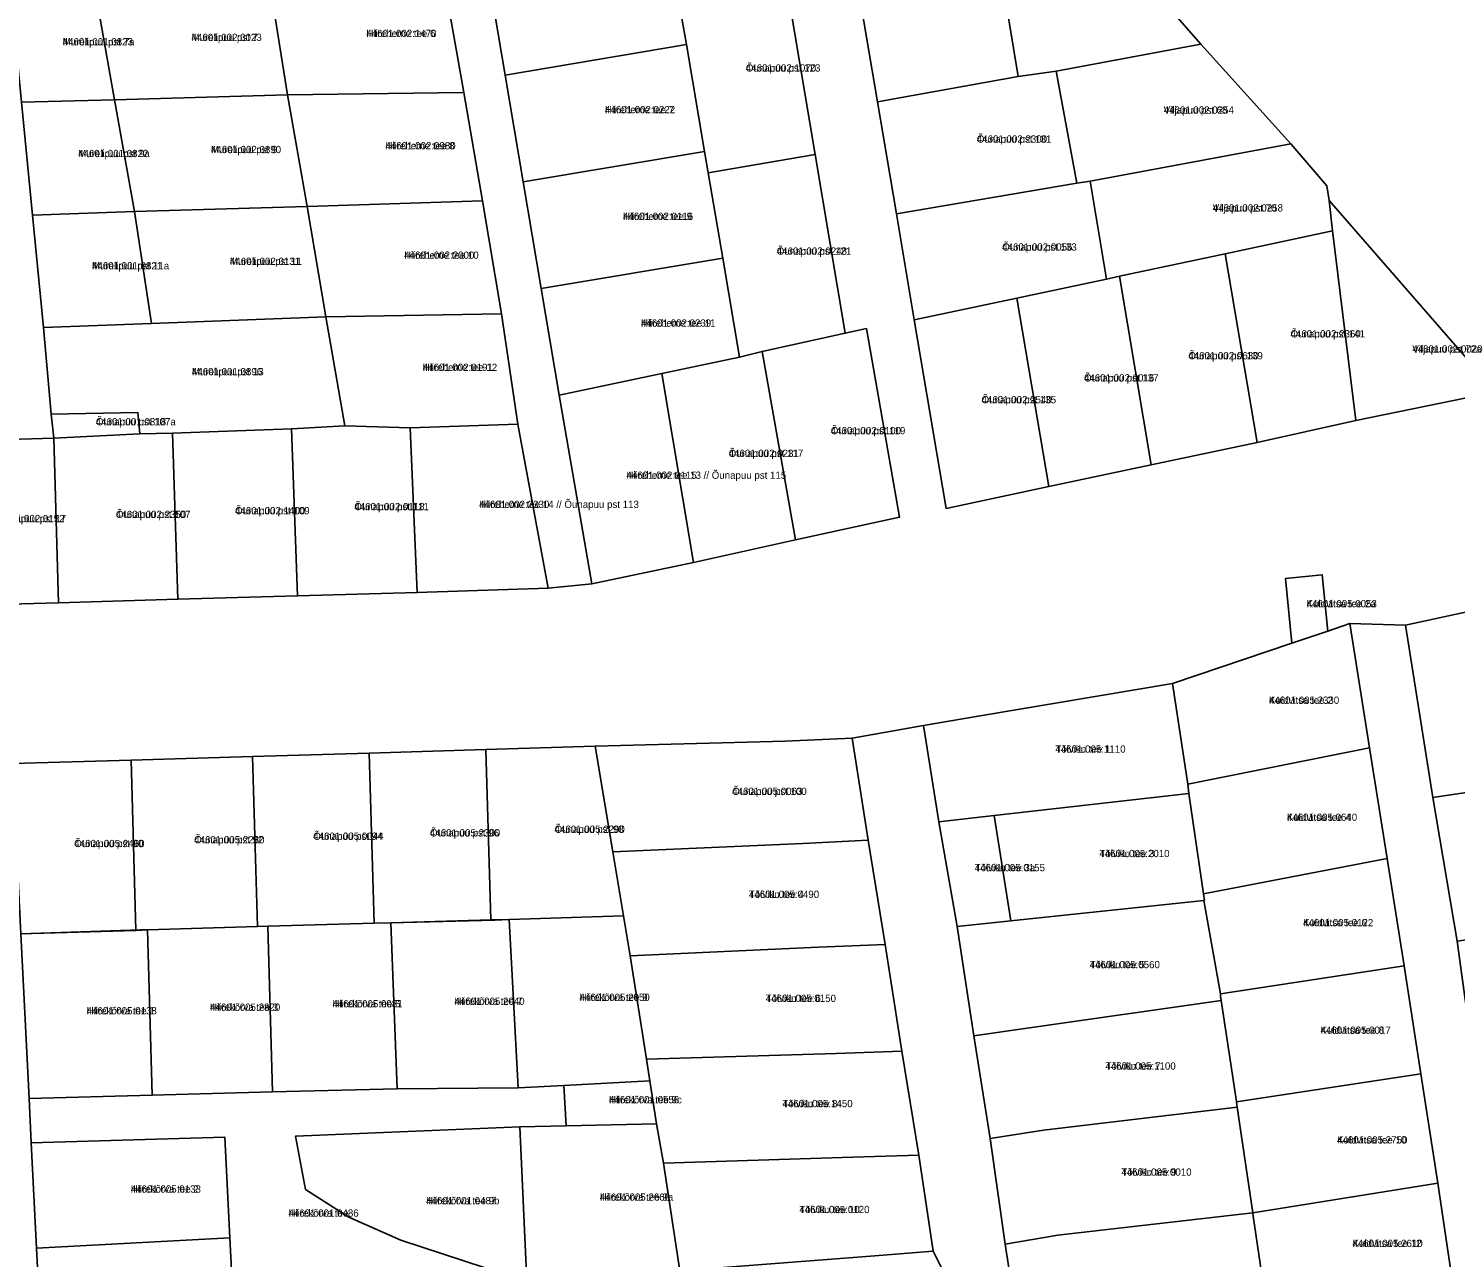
# Model space of a CAD drawing. Extents: x 551843 to 558501, y 6589003 to 6595718.
# Drawn here: x 553189.3 to 553484, y 6593051.3 to 6593305.2 of the extents above; entities that cross this region are included whole.
import ezdxf

# ---------------------------------------------------------------- set-up
doc = ezdxf.new("R2010")
doc.units = 0
for name, color, linetype in [('L_AADRESS', 7, 'Continuous'), ('PIIR', 7, 'Continuous'), ('TUNNUS', 7, 'Continuous')]:
    doc.layers.add(name, color=color, linetype=linetype)

msp = doc.modelspace()

# ---------------------------------------------------------------- linework, layer by layer
at = {"layer": 'PIIR'}
for points in [[(553431.44, 6593301.98), (553401.54, 6593296.36), (553393.68, 6593295.28), (553388.85, 6593324.58), (553408.59, 6593328.1)], [(553321.43, 6593323.96), (553323.14, 6593313.55), (553325.22, 6593301.86), (553287.76, 6593295.55), (553284.04, 6593317.59)], [(553372.85, 6593321.87), (553388.85, 6593324.58), (553393.68, 6593295.28), (553364.64, 6593290.06), (553359.64, 6593319.64)], [(553345.35, 6593317.22), (553351.79, 6593279.16), (553329.7, 6593275.35), (553328.94, 6593279.82), (553325.22, 6593301.86), (553323.14, 6593313.55)], [(553187.87, 6593289.99), (553185.68, 6593312.77), (553202.98, 6593313.47), (553207.03, 6593290.47)], [(553202.98, 6593313.47), (553239.02, 6593314.75), (553239.24, 6593314.02), (553242.8, 6593291.47), (553207.03, 6593290.47)], [(553242.8, 6593291.47), (553239.24, 6593314.02), (553275.11, 6593315.4), (553279.23, 6593292.01)], [(553287.76, 6593295.55), (553325.22, 6593301.86), (553328.94, 6593279.82), (553291.46, 6593273.51)], [(553401.54, 6593296.36), (553431.44, 6593301.98), (553449.98, 6593281.34), (553408.55, 6593273.65), (553405.8, 6593273.23)], [(553393.68, 6593295.28), (553401.54, 6593296.36), (553405.8, 6593273.23), (553368.56, 6593266.89), (553364.64, 6593290.06)], [(553190.11, 6593266.63), (553187.87, 6593289.99), (553207.03, 6593290.47), (553211.2, 6593267.42)], [(553246.86, 6593268.44), (553211.2, 6593267.42), (553207.03, 6593290.47), (553242.8, 6593291.47)], [(553246.86, 6593268.44), (553242.8, 6593291.47), (553279.23, 6593292.01), (553283.03, 6593269.62)], [(553408.55, 6593273.65), (553449.98, 6593281.34), (553457.44, 6593272.71), (553457.9, 6593269.64), (553458.6, 6593263.38), (553436.48, 6593258.67), (553414.6, 6593254.02), (553411.95, 6593253.44)], [(553328.94, 6593279.82), (553329.7, 6593275.35), (553332.67, 6593257.78), (553295.2, 6593251.47), (553291.46, 6593273.51)], [(553329.7, 6593275.35), (553351.79, 6593279.16), (553357.97, 6593242.25), (553340.79, 6593238.48), (553336.12, 6593237.33), (553332.67, 6593257.78)], [(553405.8, 6593273.23), (553408.55, 6593273.65), (553411.95, 6593253.44), (553393.42, 6593249.5), (553372.24, 6593245), (553368.56, 6593266.89)], [(553250.72, 6593245.64), (553246.86, 6593268.44), (553283.03, 6593269.62), (553286.99, 6593246.23)], [(553492.32, 6593230.16), (553463.41, 6593224.22), (553458.6, 6593263.38), (553457.9, 6593269.64)], [(553192.39, 6593243.41), (553190.11, 6593266.63), (553211.2, 6593267.42), (553214.71, 6593244.27)], [(553246.86, 6593268.44), (553250.72, 6593245.64), (553214.71, 6593244.27), (553211.2, 6593267.42)], [(553436.48, 6593258.67), (553458.6, 6593263.38), (553463.41, 6593224.22), (553443.08, 6593219.69)], [(553295.2, 6593251.47), (553332.67, 6593257.78), (553336.12, 6593237.33), (553320.1, 6593233.93), (553298.93, 6593229.44)], [(553436.48, 6593258.67), (553443.08, 6593219.69), (553421.19, 6593215.04), (553414.6, 6593254.02)], [(553400.02, 6593210.56), (553393.42, 6593249.5), (553411.95, 6593253.44), (553414.6, 6593254.02), (553421.19, 6593215.04)], [(553393.42, 6593249.5), (553400.02, 6593210.56), (553378.84, 6593206.06), (553372.24, 6593245)], [(553194.01, 6593225.56), (553192.39, 6593243.41), (553214.71, 6593244.27), (553250.72, 6593245.64), (553254.64, 6593223.14), (553243.59, 6593222.5), (553219.07, 6593221.61), (553212.31, 6593221.49), (553211.91, 6593225.86)], [(553250.72, 6593245.64), (553286.99, 6593246.23), (553290.38, 6593223.46), (553268.1, 6593222.69), (553254.64, 6593223.14)], [(553362.34, 6593243.2), (553369.22, 6593204.23), (553347.73, 6593199.6), (553340.79, 6593238.48), (553357.97, 6593242.25)], [(553320.1, 6593233.93), (553336.12, 6593237.33), (553340.79, 6593238.48), (553347.73, 6593199.6), (553326.66, 6593194.9)], [(553320.1, 6593233.93), (553326.66, 6593194.9), (553305.62, 6593190.48), (553298.93, 6593229.44)], [(553194.01, 6593225.56), (553211.91, 6593225.86), (553212.31, 6593221.49), (553194.54, 6593220.58)], [(553212.31, 6593221.49), (553219.07, 6593221.61), (553220.17, 6593187.29), (553195.51, 6593186.59), (553194.54, 6593220.58)], [(553219.07, 6593221.61), (553243.59, 6593222.5), (553244.84, 6593187.99), (553220.17, 6593187.29)], [(553243.59, 6593222.5), (553254.64, 6593223.14), (553268.1, 6593222.69), (553269.6, 6593188.68), (553244.84, 6593187.99)], [(553290.38, 6593223.46), (553296.62, 6593189.61), (553269.6, 6593188.68), (553268.1, 6593222.69)], [(553168.98, 6593219.85), (553194.54, 6593220.58), (553195.51, 6593186.59), (553172.63, 6593185.94), (553171.88, 6593186.05)], [(553456.49, 6593192.35), (553457.62, 6593180.73), (553450.21, 6593178.22), (553448.92, 6593191.6)], [(553505.14, 6593150.22), (553479.34, 6593146.36), (553473.68, 6593181.93), (553495.57, 6593186.73)], [(553428.71, 6593149.13), (553425.57, 6593169.9), (553450.21, 6593178.22), (553457.62, 6593180.73), (553462.17, 6593182.27), (553466.25, 6593156.6)], [(553377.31, 6593141.32), (553374.15, 6593161.2), (553385.43, 6593163.17), (553425.57, 6593169.9), (553428.71, 6593149.13), (553428.94, 6593147.19), (553388.71, 6593142.6)], [(553284.77, 6593121.05), (553283.76, 6593156.23), (553306.36, 6593156.94), (553309.96, 6593135.14), (553312.15, 6593121.9), (553288.59, 6593121.12)], [(553345.58, 6593157.97), (553359.4, 6593158.63), (553362.72, 6593137.54), (553349.25, 6593136.87), (553309.96, 6593135.14), (553306.36, 6593156.94)], [(553210.5, 6593154.04), (553211.49, 6593118.86), (553187.74, 6593118.19), (553185.99, 6593153.35)], [(553210.5, 6593154.04), (553235.55, 6593154.85), (553236.56, 6593119.68), (553213.88, 6593119.02), (553211.49, 6593118.86)], [(553259.66, 6593155.54), (553260.67, 6593120.37), (553238.72, 6593119.74), (553236.56, 6593119.68), (553235.55, 6593154.85)], [(553259.66, 6593155.54), (553283.76, 6593156.23), (553284.77, 6593121.05), (553264.1, 6593120.46), (553260.67, 6593120.37)], [(553466.25, 6593156.6), (553469.91, 6593133.75), (553431.95, 6593126.44), (553428.94, 6593147.19), (553428.71, 6593149.13)], [(553505.14, 6593150.22), (553505.29, 6593149.66), (553512.56, 6593120.85), (553484.38, 6593116.68), (553479.34, 6593146.36)], [(553392.15, 6593120.87), (553388.71, 6593142.6), (553428.94, 6593147.19), (553431.95, 6593126.44), (553432.15, 6593125.09), (553432.03, 6593125.08)], [(553377.31, 6593141.32), (553388.71, 6593142.6), (553392.15, 6593120.87), (553381.11, 6593119.69)], [(553312.15, 6593121.9), (553309.96, 6593135.14), (553349.25, 6593136.87), (553362.72, 6593137.54), (553366.21, 6593115.97), (553352.48, 6593115.42), (553313.54, 6593113.66)], [(553431.95, 6593126.44), (553469.91, 6593133.75), (553473.4, 6593111.59), (553435.45, 6593105.76), (553432.03, 6593125.08), (553432.15, 6593125.09)], [(553381.11, 6593119.69), (553392.15, 6593120.87), (553432.03, 6593125.08), (553435.45, 6593105.76), (553435.51, 6593105.28), (553435.65, 6593104.39), (553395.54, 6593098.68), (553384.55, 6593097.11)], [(553288.59, 6593121.12), (553312.15, 6593121.9), (553313.54, 6593113.66), (553316.91, 6593092.28), (553317.61, 6593087.83), (553299.83, 6593086.88), (553290.42, 6593086.37)], [(553189.43, 6593084.14), (553187.74, 6593118.19), (553212.45, 6593118.99), (553213.88, 6593119.02), (553214.85, 6593084.85)], [(553236.56, 6593119.68), (553238.72, 6593119.74), (553239.69, 6593085.56), (553214.85, 6593084.85), (553213.88, 6593119.02)], [(553238.72, 6593119.74), (553260.67, 6593120.37), (553264.1, 6593120.46), (553265.41, 6593086.16), (553239.69, 6593085.56)], [(553264.1, 6593120.46), (553285.58, 6593120.99), (553288.59, 6593121.12), (553290.42, 6593086.37), (553265.41, 6593086.16)], [(553316.91, 6593092.28), (553313.54, 6593113.66), (553352.48, 6593115.42), (553366.21, 6593115.97), (553369.7, 6593093.98), (553356.11, 6593093.5)], [(553438.81, 6593083.48), (553438.8, 6593083.58), (553435.65, 6593104.39), (553435.51, 6593105.28), (553435.45, 6593105.76), (553473.4, 6593111.59), (553476.88, 6593089.24)], [(553387.91, 6593075.89), (553384.55, 6593097.11), (553395.54, 6593098.68), (553435.65, 6593104.39), (553438.8, 6593083.58), (553438.81, 6593083.48), (553438.95, 6593082.36), (553398.9, 6593077.62)], [(553317.61, 6593087.83), (553316.91, 6593092.28), (553356.11, 6593093.5), (553369.7, 6593093.98), (553373.16, 6593072.45), (553359.57, 6593072.03), (553320.44, 6593070.79), (553319, 6593078.97)], [(553442.15, 6593060.53), (553438.95, 6593082.36), (553438.81, 6593083.48), (553476.88, 6593089.24), (553480.36, 6593066.71)], [(553299.83, 6593086.88), (553317.61, 6593087.83), (553319, 6593078.97), (553300.31, 6593078.56)], [(553391.01, 6593054.1), (553387.91, 6593075.89), (553398.9, 6593077.62), (553438.95, 6593082.36), (553442.15, 6593060.53), (553401.92, 6593055.91)], [(553244.46, 6593076.41), (553290.75, 6593078.29), (553292.24, 6593046.34), (553266.18, 6593054.92), (553255.47, 6593059.65), (553246.5, 6593065.41)], [(553292.24, 6593046.34), (553290.75, 6593078.29), (553300.31, 6593078.56), (553319, 6593078.97), (553320.44, 6593070.79), (553323.83, 6593048.56)], [(553190.95, 6593053.29), (553189.87, 6593075.02), (553229.88, 6593076.16), (553230.9, 6593055.36)], [(553323.83, 6593048.56), (553320.44, 6593070.79), (553359.57, 6593072.03), (553373.16, 6593072.45), (553376.17, 6593052.62), (553363.22, 6593051.62)], [(553483.64, 6593044.41), (553445.09, 6593040.29), (553442.25, 6593059.86), (553442.15, 6593060.53), (553480.36, 6593066.71)], [(553401.92, 6593055.91), (553442.15, 6593060.53), (553442.25, 6593059.86), (553445.09, 6593040.29), (553405.23, 6593034.2), (553394.33, 6593032.71), (553391.01, 6593054.1)], [(553192.04, 6593032.05), (553190.95, 6593053.29), (553230.9, 6593055.36), (553231.99, 6593034.12)]]:
    msp.add_lwpolyline(points, close=True, dxfattribs=at)
for points in [[(553492.32, 6593230.16), (553457.9, 6593269.64), (553457.44, 6593272.71), (553449.98, 6593281.34), (553431.44, 6593301.98), (553408.59, 6593328.1)], [(553359.64, 6593319.64), (553364.64, 6593290.06), (553368.56, 6593266.89), (553372.24, 6593245), (553378.84, 6593206.06), (553400.02, 6593210.56), (553421.19, 6593215.04), (553443.08, 6593219.69), (553463.41, 6593224.22), (553492.32, 6593230.16)], [(553172.63, 6593185.94), (553195.51, 6593186.59), (553220.17, 6593187.29), (553244.84, 6593187.99), (553269.6, 6593188.68), (553296.62, 6593189.61), (553305.62, 6593190.48), (553326.66, 6593194.9), (553347.73, 6593199.6), (553369.22, 6593204.23), (553362.34, 6593243.2), (553357.97, 6593242.25), (553351.79, 6593279.16), (553345.35, 6593317.22)], [(553284.04, 6593317.59), (553287.76, 6593295.55), (553291.46, 6593273.51), (553295.2, 6593251.47), (553298.93, 6593229.44), (553305.62, 6593190.48), (553296.62, 6593189.61), (553290.38, 6593223.46), (553286.99, 6593246.23), (553283.03, 6593269.62), (553279.23, 6593292.01), (553275.11, 6593315.4)], [(553187.87, 6593289.99), (553190.11, 6593266.63), (553192.39, 6593243.41), (553194.01, 6593225.56), (553194.54, 6593220.58), (553168.98, 6593219.85)], [(553495.57, 6593186.73), (553473.68, 6593181.93), (553462.17, 6593182.27), (553457.62, 6593180.73), (553456.49, 6593192.35), (553448.92, 6593191.6), (553450.21, 6593178.22), (553425.57, 6593169.9), (553385.43, 6593163.17), (553374.15, 6593161.2), (553359.4, 6593158.63), (553345.58, 6593157.97), (553306.36, 6593156.94), (553283.76, 6593156.23), (553259.66, 6593155.54), (553235.55, 6593154.85), (553210.5, 6593154.04), (553185.99, 6593153.35)], [(553483.64, 6593044.41), (553480.36, 6593066.71), (553476.88, 6593089.24), (553473.4, 6593111.59), (553469.91, 6593133.75), (553466.25, 6593156.6), (553462.17, 6593182.27), (553473.68, 6593181.93), (553479.34, 6593146.36), (553484.38, 6593116.68), (553488.36, 6593087.54), (553492.34, 6593062.25), (553495.75, 6593038.34)], [(553380.62, 6593043.69), (553376.17, 6593052.62), (553373.16, 6593072.45), (553369.7, 6593093.98), (553366.21, 6593115.97), (553362.72, 6593137.54), (553359.4, 6593158.63), (553374.15, 6593161.2), (553377.31, 6593141.32), (553381.11, 6593119.69), (553384.55, 6593097.11), (553387.91, 6593075.89), (553391.01, 6593054.1), (553394.33, 6593032.71)], [(553187.74, 6593118.19), (553189.43, 6593084.14), (553189.87, 6593075.02), (553190.95, 6593053.29), (553192.04, 6593032.05)], [(553231.99, 6593034.12), (553230.9, 6593055.36), (553229.88, 6593076.16), (553189.87, 6593075.02), (553189.43, 6593084.14), (553214.85, 6593084.85), (553239.69, 6593085.56), (553265.41, 6593086.16), (553290.42, 6593086.37), (553299.83, 6593086.88), (553300.31, 6593078.56), (553290.75, 6593078.29), (553244.46, 6593076.41), (553246.5, 6593065.41), (553255.47, 6593059.65), (553266.18, 6593054.92), (553292.24, 6593046.34)], [(553323.83, 6593048.56), (553363.22, 6593051.62), (553376.17, 6593052.62), (553380.62, 6593043.69)]]:
    msp.add_lwpolyline(points, dxfattribs=at)

# ---------------------------------------------------------------- texts
at = {"layer": 'L_AADRESS'}
for s, p in [('Murelipuu pst 7', (553222.97, 6593302.61)), ('Hiireherne tee 6', (553259.06, 6593303.43)), ('Murelipuu pst 7a', (553196.36, 6593301.7)), ('Õunapuu pst 123', (553337.46, 6593296.3)), ('Hiireherne tee 7', (553308.35, 6593287.69)), ('Viljapuu pst 68', (553423.75, 6593287.61)), ('Õunapuu pst 131', (553385.16, 6593281.62)), ('Murelipuu pst 9', (553226.97, 6593279.45)), ('Hiireherne tee 8', (553263.01, 6593280.23)), ('Murelipuu pst 9a', (553199.54, 6593278.63)), ('Viljapuu pst 70', (553433.88, 6593267.39)), ('Hiireherne tee 9', (553312.07, 6593265.65)), ('Õunapuu pst 121', (553343.84, 6593258.47)), ('Õunapuu pst 133', (553390.4, 6593259.32)), ('Murelipuu pst 11a', (553202.41, 6593255.44)), ('Murelipuu pst 11', (553230.89, 6593256.36)), ('Hiireherne tee 10', (553266.88, 6593257.63)), ('Hiireherne tee 11', (553315.8, 6593243.61)), ('Õunapuu pst 141', (553449.94, 6593241.38)), ('Viljapuu pst 72a // Õunapuu pst 141a', (553475.11, 6593238.26)), ('Õunapuu pst 139', (553428.84, 6593236.86)), ('Murelipuu pst 13', (553223.05, 6593233.57)), ('Hiireherne tee 12', (553270.71, 6593234.46)), ('Õunapuu pst 137', (553407.3, 6593232.28)), ('Õunapuu pst 135', (553386.13, 6593227.78)), ('Õunapuu pst 107a', (553203.21, 6593223.22)), ('Õunapuu pst 119', (553355, 6593221.38)), ('Õunapuu pst 117', (553333.91, 6593216.69)), ('Hiireherne tee 13 // Õunapuu pst 115', (553312.79, 6593212.18)), ('Õunapuu pst 109', (553231.96, 6593204.85)), ('Õunapuu pst 111', (553256.6, 6593205.7)), ('Hiireherne tee 14 // Õunapuu pst 113', (553282.36, 6593206.15)), ('Murelipuu pst 17', (553182.24, 6593203.22)), ('Õunapuu pst 107', (553207.36, 6593204.08)), ('Kuldvitsa tee 2a', (553453.27, 6593185.64)), ('Kuldvitsa tee 2', (553445.5, 6593165.7)), ('Tõlviku tee 1', (553401.38, 6593155.61)), ('Õunapuu pst 100', (553334.63, 6593146.88)), ('Kuldvitsa tee 4', (553449.21, 6593141.52)), ('Õunapuu pst 94', (553248.11, 6593137.61)), ('Õunapuu pst 96', (553272.21, 6593138.3)), ('Õunapuu pst 98', (553297.95, 6593139.05)), ('Õunapuu pst 90', (553198.74, 6593136.1)), ('Õunapuu pst 92', (553223.53, 6593136.88)), ('Tõlviku tee 3', (553410.46, 6593134.03)), ('Tõlviku tee 3a', (553384.73, 6593131.12)), ('Tõlviku tee 4', (553338.09, 6593125.6)), ('Kuldvitsa tee 6', (553452.54, 6593119.76)), ('Tõlviku tee 5', (553408.46, 6593111.09)), ('Hiirekõrva tee 3', (553226.79, 6593102.29)), ('Hiirekõrva tee 5', (553252.06, 6593102.99)), ('Hiirekõrva tee 7', (553277.26, 6593103.52)), ('Hiirekõrva tee 9', (553303.1, 6593104.33)), ('Tõlviku tee 6', (553341.57, 6593104.12)), ('Hiirekõrva tee 1', (553201.3, 6593101.55)), ('Kuldvitsa tee 8', (553456.14, 6593097.54)), ('Tõlviku tee 7', (553411.73, 6593090.14)), ('Hiirekõrva tee 9c', (553309.19, 6593083.19)), ('Tõlviku tee 8', (553345.01, 6593082.38)), ('Kuldvitsa tee 10', (553459.57, 6593074.88)), ('Tõlviku tee 9', (553415.01, 6593068.23)), ('Hiirekõrva tee 2', (553210.41, 6593064.73)), ('Hiirekõrva tee 9b', (553271.41, 6593062.32)), ('Hiirekõrva tee 9a', (553307.29, 6593063.06)), ('Hiirekõrva tee', (553242.99, 6593059.76)), ('Tõlviku tee 10', (553348.49, 6593060.5)), ('Kuldvitsa tee 12', (553462.74, 6593053.5))]:
    msp.add_text(s, height=1.5, dxfattribs=at).set_placement(p)
at = {"layer": 'TUNNUS'}
for s, p in [('44601:002:0023', (553222.97, 6593302.61)), ('44601:002:1470', (553259.06, 6593303.43)), ('44601:001:0823', (553196.36, 6593301.7)), ('44601:002:1070', (553337.46, 6593296.3)), ('44601:002:0222', (553308.35, 6593287.69)), ('44601:002:0254', (553423.75, 6593287.61)), ('44601:002:0890', (553226.97, 6593279.45)), ('44601:002:0980', (553263.01, 6593280.23)), ('44601:002:2300', (553385.16, 6593281.62)), ('44601:001:0822', (553199.54, 6593278.63)), ('44601:002:0258', (553433.88, 6593267.39)), ('44601:002:0116', (553312.07, 6593265.65)), ('44601:002:0248', (553343.84, 6593258.47)), ('44601:002:0056', (553390.4, 6593259.32)), ('44601:001:0821', (553202.41, 6593255.44)), ('44601:002:0131', (553230.89, 6593256.36)), ('44601:002:2000', (553266.88, 6593257.63)), ('44601:002:0239', (553315.8, 6593243.61)), ('44601:002:2360', (553449.94, 6593241.38)), ('44601:002:0020', (553475.11, 6593238.26)), ('44601:002:0630', (553428.84, 6593236.86)), ('44601:001:0896', (553223.05, 6593233.57)), ('44601:002:0191', (553270.71, 6593234.46)), ('44601:002:0016', (553407.3, 6593232.28)), ('44601:002:2540', (553386.13, 6593227.78)), ('44601:001:0818', (553203.21, 6593223.22)), ('44601:002:0100', (553355, 6593221.38)), ('44601:002:0231', (553333.91, 6593216.69)), ('44601:002:0115', (553312.79, 6593212.18)), ('44601:002:0118', (553256.6, 6593205.7)), ('44601:002:2330', (553282.36, 6593206.15)), ('44601:002:0152', (553182.24, 6593203.22)), ('44601:002:2350', (553207.36, 6593204.08)), ('44601:002:1400', (553231.96, 6593204.85)), ('44601:005:0053', (553453.27, 6593185.64)), ('44601:005:2330', (553445.5, 6593165.7)), ('44601:005:1110', (553401.38, 6593155.61)), ('44601:005:0063', (553334.63, 6593146.88)), ('44601:005:0640', (553449.21, 6593141.52)), ('44601:005:0044', (553248.11, 6593137.61)), ('44601:005:2300', (553272.21, 6593138.3)), ('44601:005:2290', (553297.95, 6593139.05)), ('44601:005:2460', (553198.74, 6593136.1)), ('44601:005:2280', (553223.53, 6593136.88)), ('44601:005:2010', (553410.46, 6593134.03)), ('44601:005:0155', (553384.73, 6593131.12)), ('44601:005:0490', (553338.09, 6593125.6)), ('44601:005:0122', (553452.54, 6593119.76)), ('44601:005:0560', (553408.46, 6593111.09)), ('44601:005:2820', (553226.79, 6593102.29)), ('44601:005:0081', (553252.06, 6593102.99)), ('44601:005:2040', (553277.26, 6593103.52)), ('44601:005:2050', (553303.1, 6593104.33)), ('44601:005:0150', (553341.57, 6593104.12)), ('44601:005:0138', (553201.3, 6593101.55)), ('44601:005:0017', (553456.14, 6593097.54)), ('44601:005:1100', (553411.73, 6593090.14)), ('44601:001:0556', (553309.19, 6593083.19)), ('44601:005:1450', (553345.01, 6593082.38)), ('44601:005:2750', (553459.57, 6593074.88)), ('44601:005:0010', (553415.01, 6593068.23)), ('44601:005:0133', (553210.41, 6593064.73)), ('44601:001:0487', (553271.41, 6593062.32)), ('44601:005:2660', (553307.29, 6593063.06)), ('44601:001:0486', (553242.99, 6593059.76)), ('44601:005:0120', (553348.49, 6593060.5)), ('44601:005:2610', (553462.74, 6593053.5))]:
    msp.add_text(s, height=1.5, dxfattribs=at).set_placement(p)

doc.saveas('drawing.dxf')
